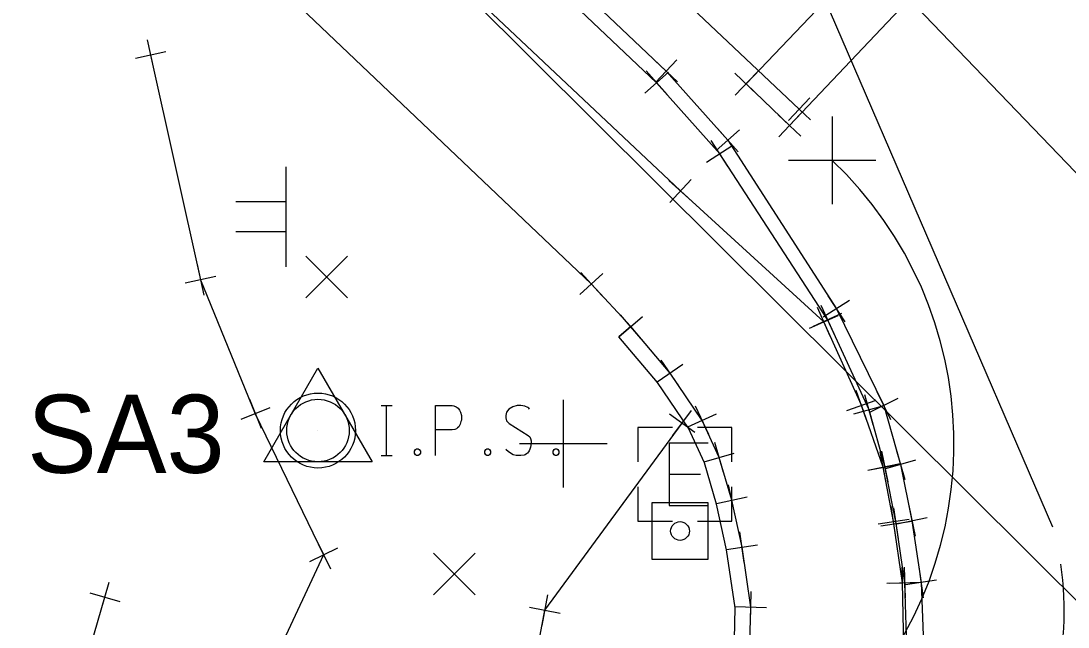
# Model space of a CAD drawing. Extents: x 1475580 to 1482245, y 377937 to 382467.
# Drawn here: x 1481380 to 1481413.5, y 378219.8 to 378239.2 of the extents above; entities that cross this region are included whole.
import ezdxf

# ---------------------------------------------------------------- set-up
doc = ezdxf.new("R2010")
doc.units = 0
for name, color, linetype in [('BD_X_Building', 7, 'Continuous'), ('Default', 7, 'Continuous'), ('DR_X_Elev_Flow', 7, 'Continuous'), ('DT_X_Contour_Minor', 7, 'Continuous'), ('DT_X_Void', 7, 'Continuous'), ('GE_X_Cells', 7, 'Continuous'), ('PV_X_Curb', 7, 'Continuous'), ('RD_X_Cells', 7, 'Continuous'), ('RW_P_Esmt_SH', 7, 'Continuous'), ('SG_X_Poles', 7, 'Continuous'), ('SG_X_Wiring', 7, 'Continuous'), ('SN_X_Private', 7, 'Continuous'), ('SV_X_Shot_Marker', 7, 'Continuous'), ('SV_X_Text_Description', 7, 'Continuous'), ('UT_X_Gas_Cells', 7, 'Continuous'), ('UT_X_Water', 7, 'Continuous'), ('VG_X_Cells', 7, 'Continuous'), ('XS_X_Ground_Line', 7, 'Continuous')]:
    doc.layers.add(name, color=color, linetype=linetype)

msp = doc.modelspace()

# ---------------------------------------------------------------- linework, layer by layer
at = {"layer": 'BD_X_Building'}
msp.add_lwpolyline([(1481400.19, 378221.971), (1481401.99, 378221.971), (1481401.99, 378223.771), (1481400.19, 378223.771)], close=True, dxfattribs=at)
msp.add_circle((1481401.09, 378222.871), 0.3, dxfattribs=at)
at = {"layer": 'DR_X_Elev_Flow'}
msp.add_lwpolyline([(1481424.786, 378259.815), (1481426.129, 378258.574), (1481404.591, 378235.85), (1481403.205, 378237.182)], close=True, dxfattribs=at)
at = {"layer": 'DT_X_Contour_Minor'}
for points in [[(1481391.525, 378226.888), (1481391.878, 378226.888)], [(1481391.701, 378225.288), (1481391.701, 378226.888)], [(1481393.267, 378225.288), (1481393.267, 378226.888), (1481393.796, 378226.888), (1481393.851, 378226.876), (1481393.928, 378226.85), (1481393.961, 378226.825), (1481393.994, 378226.8), (1481394.038, 378226.737), (1481394.071, 378226.674), (1481394.093, 378226.573), (1481394.093, 378226.422), (1481394.082, 378226.372), (1481394.06, 378226.296), (1481394.016, 378226.208), (1481393.972, 378226.17), (1481393.939, 378226.145), (1481393.884, 378226.12), (1481393.796, 378226.107), (1481393.267, 378226.107)], [(1481396.276, 378226.775), (1481396.254, 378226.8), (1481396.221, 378226.825), (1481396.122, 378226.863), (1481396, 378226.888), (1481395.912, 378226.888), (1481395.879, 378226.888), (1481395.736, 378226.85), (1481395.615, 378226.775), (1481395.537, 378226.674), (1481395.515, 378226.573), (1481395.515, 378226.498), (1481395.537, 378226.397), (1481395.626, 378226.309), (1481396.232, 378225.931), (1481396.287, 378225.881), (1481396.309, 378225.83), (1481396.331, 378225.755), (1481396.331, 378225.679), (1481396.32, 378225.603), (1481396.309, 378225.553), (1481396.287, 378225.49), (1481396.265, 378225.44), (1481396.243, 378225.402), (1481396.21, 378225.364), (1481396.177, 378225.339), (1481396.133, 378225.314), (1481396.1, 378225.301), (1481396, 378225.288), (1481395.846, 378225.288), (1481395.747, 378225.314), (1481395.603, 378225.402), (1481395.515, 378225.477)], [(1481392.66, 378225.503), (1481392.715, 378225.503), (1481392.749, 378225.477), (1481392.782, 378225.427), (1481392.782, 378225.364), (1481392.749, 378225.314), (1481392.715, 378225.288), (1481392.66, 378225.288), (1481392.627, 378225.314), (1481392.594, 378225.364), (1481392.594, 378225.427), (1481392.627, 378225.477), (1481392.66, 378225.503)], [(1481394.909, 378225.503), (1481394.964, 378225.503), (1481394.997, 378225.477), (1481395.03, 378225.427), (1481395.03, 378225.364), (1481394.997, 378225.314), (1481394.964, 378225.288), (1481394.909, 378225.288), (1481394.876, 378225.314), (1481394.843, 378225.364), (1481394.843, 378225.427), (1481394.876, 378225.477), (1481394.909, 378225.503)], [(1481397.092, 378225.503), (1481397.147, 378225.503), (1481397.18, 378225.477), (1481397.213, 378225.427), (1481397.213, 378225.364), (1481397.18, 378225.314), (1481397.147, 378225.288), (1481397.092, 378225.288), (1481397.058, 378225.314), (1481397.026, 378225.364), (1481397.026, 378225.427), (1481397.058, 378225.477), (1481397.092, 378225.503)], [(1481391.525, 378225.288), (1481391.878, 378225.288)]]:
    msp.add_lwpolyline(points, dxfattribs=at)
msp.add_circle((1481389.506, 378226.087), 1.2, dxfattribs=at)
at = {"layer": 'DT_X_Void'}
for p, q in [((1481387.774, 378225.087), (1481389.506, 378228.087)), ((1481389.506, 378228.087), (1481391.238, 378225.087)), ((1481389.506, 378226.087), (1481389.506, 378226.087)), ((1481391.238, 378225.087), (1481387.774, 378225.087))]:
    msp.add_line(p, q, dxfattribs=at)
msp.add_circle((1481389.506, 378226.087), 1, dxfattribs=at)
at = {"layer": 'GE_X_Cells'}
for p, q in [((1481405.958, 378236.133), (1481405.958, 378233.333)), ((1481407.358, 378234.733), (1481404.558, 378234.733)), ((1481397.354, 378227.065), (1481397.354, 378224.265)), ((1481398.754, 378225.665), (1481395.954, 378225.665))]:
    msp.add_line(p, q, dxfattribs=at)
msp.add_arc((1481397.354, 378225.665), 12.5, 316.5006, 46.5006, dxfattribs=at)
at = {"layer": 'PV_X_Curb'}
for p, q in [((1481389.114, 378230.331), (1481390.448, 378231.666)), ((1481389.114, 378231.666), (1481390.448, 378230.331)), ((1481393.204, 378220.827), (1481394.537, 378222.162)), ((1481393.204, 378222.162), (1481394.537, 378220.827))]:
    msp.add_line(p, q, dxfattribs=at)
at = {"layer": 'RD_X_Cells'}
msp.add_line((1481399.511, 378229.414), (1481399.13, 378229.091), dxfattribs=at)
for points in [[(1481295.832, 378090.579), (1481298.146, 378095.211), (1481299.307, 378096.99), (1481300.547, 378098.473), (1481318.958, 378117.763), (1481339.451, 378139.219), (1481360.186, 378160.992), (1481380.782, 378182.816), (1481399.814, 378203.034), (1481403.727, 378204.629), (1481405.126, 378207.012), (1481405.96, 378208.758), (1481406.475, 378210.214), (1481407.109, 378212.396), (1481407.852, 378215.072), (1481408.098, 378217.052), (1481408.252, 378219.179), (1481408.208, 378221.211), (1481407.921, 378223.176), (1481407.59, 378224.91), (1481406.894, 378226.898), (1481405.69, 378229.567), (1481401.105, 378233.755), (1481377.226, 378256.245)], [(1481316.103, 378120.507), (1481336.541, 378141.928), (1481357.274, 378163.762), (1481377.97, 378185.403), (1481397.041, 378205.764), (1481398.555, 378207.462), (1481399.878, 378209.203), (1481401.044, 378210.964), (1481401.477, 378211.903), (1481402.311, 378214.059), (1481402.765, 378215.748), (1481403.11, 378217.011), (1481403.316, 378218.875), (1481403.358, 378220.438), (1481403.073, 378222.355), (1481402.746, 378223.855), (1481402.345, 378225.225), (1481401.798, 378226.412), (1481400.771, 378227.928), (1481399.511, 378229.414), (1481398.252, 378230.777), (1481374.491, 378253.376)], [(1481396.676, 378206.106), (1481398.169, 378207.78), (1481399.47, 378209.493), (1481400.606, 378211.209), (1481401.017, 378212.098), (1481401.835, 378214.214), (1481402.282, 378215.878), (1481402.617, 378217.104), (1481402.817, 378218.909), (1481402.857, 378220.408), (1481402.581, 378222.265), (1481402.262, 378223.731), (1481401.875, 378225.049), (1481401.361, 378226.165), (1481400.372, 378227.625), (1481399.136, 378229.083), (1481399.129, 378229.091)]]:
    msp.add_lwpolyline(points, dxfattribs=at)
at = {"layer": 'RW_P_Esmt_SH'}
for p, q in [((1481403.431, 378245.117), (1481447.014, 378199.625)), ((1481403.489, 378245.057), (1481413.007, 378223.008))]:
    msp.add_line(p, q, dxfattribs=at)
msp.add_arc((1481403.842, 378220.356), 9.541, 319.6578, 8.7474, dxfattribs=at)
at = {"layer": 'SG_X_Poles'}
msp.add_line((1481285.661, 378348.172), (1481442.911, 378191.64), dxfattribs=at)
at = {"layer": 'SG_X_Wiring'}
for p, q in [((1481400.745, 378224.688), (1481401.745, 378224.688)), ((1481401.245, 378224.688), (1481401.245, 378224.688))]:
    msp.add_line(p, q, dxfattribs=at)
for points in [[(1481400.845, 378226.188), (1481399.745, 378226.188), (1481399.745, 378225.088)], [(1481402.745, 378225.088), (1481402.745, 378226.188), (1481401.645, 378226.188)], [(1481401.995, 378225.688), (1481400.745, 378225.688), (1481400.745, 378223.688), (1481401.995, 378223.688)], [(1481399.745, 378224.288), (1481399.745, 378223.188), (1481400.845, 378223.188)], [(1481401.645, 378223.188), (1481402.745, 378223.188), (1481402.745, 378224.288)]]:
    msp.add_lwpolyline(points, dxfattribs=at)
at = {"layer": 'SN_X_Private'}
msp.add_lwpolyline([(1481384.151, 378238.104), (1481385.75, 378230.909), (1481387.5, 378226.626), (1481389.686, 378222.108), (1481386.825, 378215.987), (1481380.576, 378206.43), (1481371.218, 378195.508), (1481348.71, 378172.03), (1481329.203, 378150.625), (1481307.073, 378125.53), (1481304.865, 378122.949), (1481305.359, 378117.802), (1481305.35, 378117.797), (1481318.973, 378131.952), (1481334.718, 378149.536), (1481352.628, 378167.468), (1481374.047, 378188.656), (1481394.369, 378207.529), (1481396.766, 378220.338), (1481401.158, 378226.327)], dxfattribs=at)
at = {"layer": 'SV_X_Shot_Marker'}
msp.add_lwpolyline([(1481404.9, 378236.37), (1481341.278, 378296.442), (1481336.457, 378301.165), (1481331.567, 378306.204), (1481326.38, 378311.756), (1481274.04, 378370.244)], dxfattribs=at)
at = {"layer": 'SV_X_Text_Description'}
msp.add_lwpolyline([(1481320.414, 378116.343), (1481340.859, 378137.833), (1481361.576, 378159.638), (1481382.233, 378181.406), (1481396.451, 378196.415), (1481396.638, 378196.668), (1481400.969, 378200.976), (1481402.186, 378202.435), (1481403.797, 378204.569), (1481405.194, 378206.962), (1481406.038, 378208.715), (1481406.627, 378210.066), (1481407.935, 378215.059), (1481408.196, 378217.135), (1481408.344, 378219.163), (1481408.285, 378221.217), (1481408.008, 378223.113), (1481407.647, 378224.931), (1481407.137, 378226.752), (1481405.813, 378229.639), (1481402.359, 378234.946), (1481400.342, 378237.22), (1481378.635, 378257.78)], dxfattribs=at)
at = {"layer": 'UT_X_Gas_Cells'}
for p, q in [((1481384.042, 378238.592), (1481384.259, 378237.616)), ((1481384.639, 378238.212), (1481383.663, 378237.995)), ((1481384.151, 378238.104), (1481384.151, 378238.104)), ((1481400.282, 378237.931), (1481401.008, 378237.243)), ((1481400.989, 378237.95), (1481400.301, 378237.224)), ((1481399.968, 378236.888), (1481400.716, 378237.552)), ((1481400.674, 378236.846), (1481400.01, 378237.594)), ((1481400.645, 378237.587), (1481400.645, 378237.587)), ((1481403.566, 378236.835), (1481402.845, 378237.528)), ((1481402.859, 378236.821), (1481403.552, 378237.542)), ((1481400.342, 378237.22), (1481400.342, 378237.22)), ((1481403.205, 378237.182), (1481403.205, 378237.182)), ((1481405.264, 378236.027), (1481404.537, 378236.713)), ((1481404.557, 378236.006), (1481405.243, 378236.733)), ((1481404.953, 378235.506), (1481404.228, 378236.194)), ((1481404.934, 378236.213), (1481404.247, 378235.487)), ((1481404.9, 378236.37), (1481404.9, 378236.37)), ((1481404.591, 378235.85), (1481404.591, 378235.85)), ((1481402.99, 378235.715), (1481402.245, 378235.049)), ((1481402.284, 378235.755), (1481402.951, 378235.009)), ((1481401.94, 378234.673), (1481402.778, 378235.219)), ((1481402.632, 378234.527), (1481402.086, 378235.365)), ((1481402.618, 378235.382), (1481402.618, 378235.382)), ((1481402.359, 378234.946), (1481402.359, 378234.946)), ((1481400.768, 378233.386), (1481401.442, 378234.124)), ((1481401.474, 378233.418), (1481400.736, 378234.092)), ((1481401.105, 378233.755), (1481401.105, 378233.755)), ((1481385.642, 378231.397), (1481385.859, 378230.421)), ((1481397.884, 378230.438), (1481398.619, 378231.117)), ((1481398.591, 378230.41), (1481397.912, 378231.145)), ((1481386.238, 378231.017), (1481385.262, 378230.8)), ((1481385.75, 378230.909), (1481385.75, 378230.909)), ((1481398.252, 378230.777), (1481398.252, 378230.777)), ((1481406.515, 378230.252), (1481405.674, 378229.711)), ((1481405.823, 378230.402), (1481406.365, 378229.561)), ((1481399.834, 378229.033), (1481399.188, 378229.795)), ((1481405.234, 378229.361), (1481406.146, 378229.772)), ((1481405.359, 378229.431), (1481406.268, 378229.847)), ((1481405.896, 378229.111), (1481405.484, 378230.022)), ((1481406.022, 378229.184), (1481405.605, 378230.093)), ((1481406.094, 378229.981), (1481406.094, 378229.981)), ((1481399.13, 378229.091), (1481399.893, 378229.737)), ((1481405.69, 378229.567), (1481405.69, 378229.567)), ((1481405.813, 378229.639), (1481405.813, 378229.639)), ((1481399.511, 378229.414), (1481399.511, 378229.414)), ((1481400.357, 378227.647), (1481401.184, 378228.208)), ((1481401.051, 378227.514), (1481400.49, 378228.342)), ((1481400.771, 378227.928), (1481400.771, 378227.928)), ((1481387.311, 378227.089), (1481387.689, 378226.163)), ((1481407.059, 378226.426), (1481406.729, 378227.37)), ((1481407.272, 378226.271), (1481407.002, 378227.234)), ((1481408.055, 378227.109), (1481407.156, 378226.669)), ((1481407.386, 378227.338), (1481407.825, 378226.44)), ((1481387.963, 378226.815), (1481387.037, 378226.437)), ((1481402.007, 378225.958), (1481401.589, 378226.866)), ((1481406.422, 378226.733), (1481407.366, 378227.064)), ((1481406.655, 378226.617), (1481407.618, 378226.887)), ((1481406.894, 378226.898), (1481406.894, 378226.898)), ((1481407.137, 378226.752), (1481407.137, 378226.752)), ((1481407.605, 378226.889), (1481407.605, 378226.889)), ((1481387.5, 378226.626), (1481387.5, 378226.626)), ((1481400.755, 378226.623), (1481401.561, 378226.031)), ((1481400.862, 378225.924), (1481401.454, 378226.73)), ((1481401.344, 378226.203), (1481402.252, 378226.621)), ((1481401.158, 378226.327), (1481401.158, 378226.327)), ((1481401.798, 378226.412), (1481401.798, 378226.412)), ((1481402.485, 378224.745), (1481402.204, 378225.705)), ((1481407.744, 378224.441), (1481407.549, 378225.422)), ((1481408.006, 378225.479), (1481408.28, 378224.517)), ((1481401.865, 378225.084), (1481402.824, 378225.366)), ((1481402.345, 378225.225), (1481402.345, 378225.225)), ((1481407.684, 378224.419), (1481407.496, 378225.401)), ((1481408.624, 378225.135), (1481407.662, 378224.861)), ((1481407.099, 378224.817), (1481408.081, 378225.004)), ((1481407.156, 378224.834), (1481408.137, 378225.029)), ((1481407.59, 378224.91), (1481407.59, 378224.91)), ((1481407.647, 378224.931), (1481407.647, 378224.931)), ((1481408.143, 378224.998), (1481408.143, 378224.998)), ((1481402.853, 378223.367), (1481402.64, 378224.344)), ((1481402.258, 378223.749), (1481403.235, 378223.962)), ((1481402.746, 378223.855), (1481402.746, 378223.855)), ((1481407.993, 378222.681), (1481407.849, 378223.671)), ((1481408.08, 378222.618), (1481407.935, 378223.608)), ((1481408.411, 378223.684), (1481408.611, 378222.705)), ((1481407.426, 378223.104), (1481408.416, 378223.248)), ((1481407.513, 378223.041), (1481408.502, 378223.185)), ((1481407.921, 378223.176), (1481407.921, 378223.176)), ((1481408.008, 378223.113), (1481408.008, 378223.113)), ((1481409.001, 378223.294), (1481408.021, 378223.095)), ((1481408.511, 378223.195), (1481408.511, 378223.195)), ((1481403.147, 378221.86), (1481403, 378222.849)), ((1481389.468, 378222.558), (1481389.904, 378221.658)), ((1481402.579, 378222.281), (1481403.568, 378222.428)), ((1481390.136, 378222.326), (1481389.236, 378221.89)), ((1481389.686, 378222.108), (1481389.686, 378222.108)), ((1481403.073, 378222.355), (1481403.073, 378222.355)), ((1481408.219, 378220.711), (1481408.197, 378221.711)), ((1481408.299, 378220.717), (1481408.27, 378221.716)), ((1481408.727, 378221.72), (1481408.872, 378220.731)), ((1481382.55, 378220.279), (1481382.828, 378221.239)), ((1481407.708, 378221.2), (1481408.708, 378221.222)), ((1481407.785, 378221.202), (1481408.784, 378221.231)), ((1481408.208, 378221.211), (1481408.208, 378221.211)), ((1481408.285, 378221.217), (1481408.285, 378221.217)), ((1481409.295, 378221.298), (1481408.305, 378221.153)), ((1481408.8, 378221.225), (1481408.8, 378221.225)), ((1481382.209, 378220.898), (1481383.169, 378220.62)), ((1481382.689, 378220.759), (1481382.689, 378220.759)), ((1481396.674, 378219.846), (1481396.858, 378220.829)), ((1481403.344, 378219.938), (1481403.371, 378220.938)), ((1481396.275, 378220.43), (1481397.258, 378220.246)), ((1481402.858, 378220.451), (1481403.858, 378220.425)), ((1481403.358, 378220.438), (1481403.358, 378220.438)), ((1481396.766, 378220.338), (1481396.766, 378220.338))]:
    msp.add_line(p, q, dxfattribs=at)
at = {"layer": 'UT_X_Water'}
msp.add_lwpolyline([(1481273.858, 378103.679), (1481275.267, 378102.296), (1481278.9, 378104.223), (1481289.925, 378117.296), (1481310.885, 378138.687), (1481331.521, 378162.277), (1481355.202, 378185.307), (1481374.349, 378205.986), (1481377.56, 378209.873), (1481381.344, 378216.118), (1481382.689, 378220.759)], dxfattribs=at)
at = {"layer": 'VG_X_Cells'}
for p, q in [((1481388.482, 378234.528), (1481388.482, 378231.328)), ((1481388.482, 378233.408), (1481386.882, 378233.408)), ((1481388.482, 378232.928), (1481388.482, 378232.928)), ((1481388.482, 378232.448), (1481386.882, 378232.448))]:
    msp.add_line(p, q, dxfattribs=at)
at = {"layer": 'XS_X_Ground_Line'}
msp.add_lwpolyline([(1481378.945, 378258.155), (1481400.645, 378237.587), (1481402.618, 378235.382), (1481406.094, 378229.981), (1481407.605, 378226.889), (1481408.143, 378224.998), (1481408.511, 378223.195), (1481408.8, 378221.225), (1481408.884, 378219.249), (1481408.749, 378217.035), (1481408.505, 378214.96), (1481407.93, 378212.129), (1481407.222, 378209.865), (1481406.648, 378208.414), (1481405.745, 378206.754), (1481404.246, 378204.362), (1481402.639, 378202.127), (1481401.324, 378200.63), (1481397.156, 378196.265), (1481398.125, 378195.357), (1481383.86, 378180.08), (1481363.147, 378158.397), (1481342.53, 378136.572), (1481321.954, 378114.976)], dxfattribs=at)

# ---------------------------------------------------------------- texts
at = {"layer": 'Default'}
msp.add_text('SA3', height=2.5, dxfattribs=at).set_placement((1481380.201, 378224.733))

doc.saveas('drawing.dxf')
